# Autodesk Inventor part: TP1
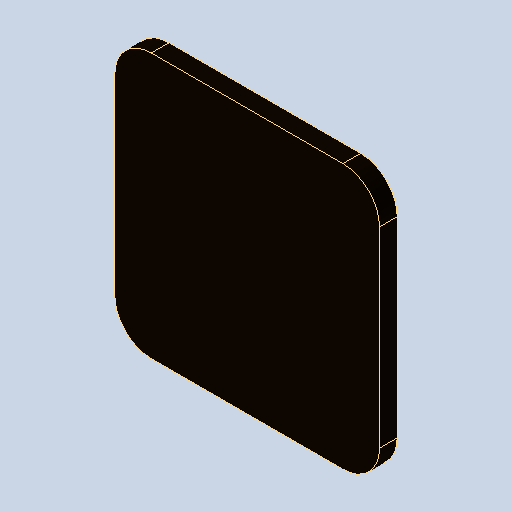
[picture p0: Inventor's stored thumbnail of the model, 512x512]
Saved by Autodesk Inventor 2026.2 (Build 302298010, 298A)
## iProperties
Created: 2026-10
Part Number: TP1
Material: Générique
Document SubType Name: Modeling
Designer: mel
Density: 1 g/cm^3
Appearance: Par défaut
Author: mel
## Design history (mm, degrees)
feature "Base1"
node "Solide1"
